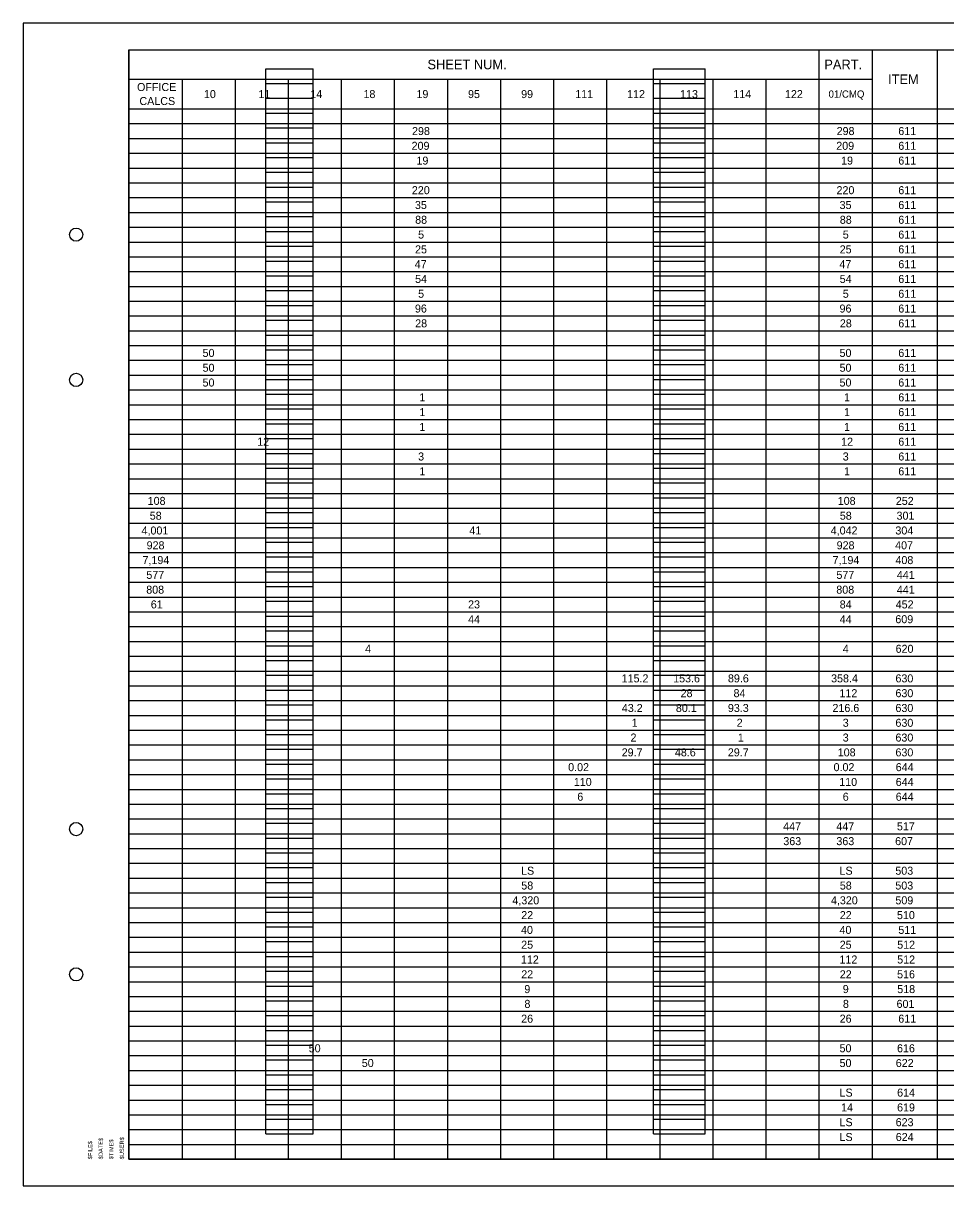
# Model space of a CAD drawing. Extents: x -16 to 102, y -13 to 9.
# Drawn here: x 27.05 to 44.51, y -12.91 to 9.09 of the extents above; entities that cross this region are included whole.
import ezdxf

# ---------------------------------------------------------------- set-up
doc = ezdxf.new("R2010")
doc.units = 0
for name, color, linetype in [('SH_Border', 7, 'Continuous'), ('SH_Cut_Line', 7, 'Continuous'), ('SH_Data', 7, 'Continuous'), ('TX_P_1', 7, 'Continuous'), ('TX_P_Misc', 7, 'Continuous')]:
    doc.layers.add(name, color=color, linetype=linetype)

msp = doc.modelspace()

# ---------------------------------------------------------------- linework, layer by layer
at = {"layer": 'SH_Border'}
msp.add_lwpolyline([(29.054, 8.593), (60.554, 8.593), (60.554, -12.407), (29.054, -12.407)], close=True, dxfattribs=at)
for centre in [(28.054, 5.093), (28.054, 2.343), (28.054, -6.157), (28.054, -8.907)]:
    msp.add_circle(centre, 0.125, dxfattribs=at)
at = {"layer": 'SH_Cut_Line'}
msp.add_lwpolyline([(27.054, -12.907), (61.054, -12.907), (61.054, 9.093), (27.054, 9.093)], close=True, dxfattribs=at)
at = {"layer": 'SH_Data'}
for p, q in [((31.642, -11.927), (31.642, 8.233)), ((31.642, 8.233), (32.542, 8.233)), ((32.542, -11.927), (32.542, 8.233)), ((38.982, -11.927), (38.982, 8.233)), ((38.982, 8.233), (39.962, 8.233)), ((39.962, -11.927), (39.962, 8.233)), ((31.642, 7.953), (32.542, 7.953)), ((38.982, 7.953), (39.962, 7.953)), ((31.642, 7.673), (32.542, 7.673)), ((38.982, 7.673), (39.962, 7.673)), ((31.642, 7.393), (32.542, 7.393)), ((38.982, 7.393), (39.962, 7.393)), ((31.642, 7.113), (32.542, 7.113)), ((38.982, 7.113), (39.962, 7.113)), ((31.642, 6.833), (32.542, 6.833)), ((38.982, 6.833), (39.962, 6.833)), ((31.642, 6.553), (32.542, 6.553)), ((38.982, 6.553), (39.962, 6.553)), ((31.642, 6.273), (32.542, 6.273)), ((38.982, 6.273), (39.962, 6.273)), ((31.642, 5.993), (32.542, 5.993)), ((38.982, 5.993), (39.962, 5.993)), ((31.642, 5.713), (32.542, 5.713)), ((38.982, 5.713), (39.962, 5.713)), ((31.642, 5.433), (32.542, 5.433)), ((38.982, 5.433), (39.962, 5.433)), ((31.642, 5.153), (32.542, 5.153)), ((38.982, 5.153), (39.962, 5.153)), ((31.642, 4.873), (32.542, 4.873)), ((38.982, 4.873), (39.962, 4.873)), ((31.642, 4.593), (32.542, 4.593)), ((38.982, 4.593), (39.962, 4.593)), ((31.642, 4.313), (32.542, 4.313)), ((38.982, 4.313), (39.962, 4.313)), ((31.642, 4.033), (32.542, 4.033)), ((38.982, 4.033), (39.962, 4.033)), ((31.642, 3.753), (32.542, 3.753)), ((38.982, 3.753), (39.962, 3.753)), ((31.642, 3.473), (32.542, 3.473)), ((38.982, 3.473), (39.962, 3.473)), ((31.642, 3.193), (32.542, 3.193)), ((38.982, 3.193), (39.962, 3.193)), ((31.642, 2.913), (32.542, 2.913)), ((38.982, 2.913), (39.962, 2.913)), ((31.642, 2.633), (32.542, 2.633)), ((38.982, 2.633), (39.962, 2.633)), ((31.642, 2.353), (32.542, 2.353)), ((38.982, 2.353), (39.962, 2.353)), ((31.642, 2.073), (32.542, 2.073)), ((38.982, 2.073), (39.962, 2.073)), ((31.642, 1.793), (32.542, 1.793)), ((38.982, 1.793), (39.962, 1.793)), ((31.642, 1.513), (32.542, 1.513)), ((38.982, 1.513), (39.962, 1.513)), ((31.642, 1.233), (32.542, 1.233)), ((38.982, 1.233), (39.962, 1.233)), ((31.642, 0.953), (32.542, 0.953)), ((38.982, 0.953), (39.962, 0.953)), ((31.642, 0.673), (32.542, 0.673)), ((38.982, 0.673), (39.962, 0.673)), ((31.642, 0.393), (32.542, 0.393)), ((38.982, 0.393), (39.962, 0.393)), ((31.642, 0.113), (32.542, 0.113)), ((38.982, 0.113), (39.962, 0.113)), ((31.642, -0.167), (32.542, -0.167)), ((38.982, -0.167), (39.962, -0.167)), ((31.642, -0.447), (32.542, -0.447)), ((38.982, -0.447), (39.962, -0.447)), ((31.642, -0.727), (32.542, -0.727)), ((38.982, -0.727), (39.962, -0.727)), ((31.642, -1.007), (32.542, -1.007)), ((38.982, -1.007), (39.962, -1.007)), ((31.642, -1.287), (32.542, -1.287)), ((38.982, -1.287), (39.962, -1.287)), ((31.642, -1.567), (32.542, -1.567)), ((38.982, -1.567), (39.962, -1.567)), ((31.642, -1.847), (32.542, -1.847)), ((38.982, -1.847), (39.962, -1.847)), ((31.642, -2.127), (32.542, -2.127)), ((38.982, -2.127), (39.962, -2.127)), ((31.642, -2.407), (32.542, -2.407)), ((38.982, -2.407), (39.962, -2.407)), ((31.642, -2.687), (32.542, -2.687)), ((38.982, -2.687), (39.962, -2.687)), ((31.642, -2.967), (32.542, -2.967)), ((38.982, -2.967), (39.962, -2.967)), ((31.642, -3.247), (32.542, -3.247)), ((38.982, -3.247), (39.962, -3.247)), ((31.642, -3.527), (32.542, -3.527)), ((38.982, -3.527), (39.962, -3.527)), ((31.642, -3.807), (32.542, -3.807)), ((38.982, -3.807), (39.962, -3.807)), ((31.642, -4.087), (32.542, -4.087)), ((38.982, -4.087), (39.962, -4.087)), ((31.642, -4.367), (32.542, -4.367)), ((38.982, -4.367), (39.962, -4.367)), ((31.642, -4.647), (32.542, -4.647)), ((38.982, -4.647), (39.962, -4.647)), ((31.642, -4.927), (32.542, -4.927)), ((38.982, -4.927), (39.962, -4.927)), ((31.642, -5.207), (32.542, -5.207)), ((38.982, -5.207), (39.962, -5.207)), ((31.642, -5.487), (32.542, -5.487)), ((38.982, -5.487), (39.962, -5.487)), ((31.642, -5.767), (32.542, -5.767)), ((38.982, -5.767), (39.962, -5.767)), ((31.642, -6.047), (32.542, -6.047)), ((38.982, -6.047), (39.962, -6.047)), ((31.642, -6.327), (32.542, -6.327)), ((38.982, -6.327), (39.962, -6.327)), ((31.642, -6.607), (32.542, -6.607)), ((38.982, -6.607), (39.962, -6.607)), ((31.642, -6.887), (32.542, -6.887)), ((38.982, -6.887), (39.962, -6.887)), ((31.642, -7.167), (32.542, -7.167)), ((38.982, -7.167), (39.962, -7.167)), ((31.642, -7.447), (32.542, -7.447)), ((38.982, -7.447), (39.962, -7.447)), ((31.642, -7.727), (32.542, -7.727)), ((38.982, -7.727), (39.962, -7.727)), ((31.642, -8.007), (32.542, -8.007)), ((38.982, -8.007), (39.962, -8.007)), ((31.642, -8.287), (32.542, -8.287)), ((38.982, -8.287), (39.962, -8.287)), ((31.642, -8.567), (32.542, -8.567)), ((38.982, -8.567), (39.962, -8.567)), ((31.642, -8.847), (32.542, -8.847)), ((38.982, -8.847), (39.962, -8.847)), ((31.642, -9.127), (32.542, -9.127)), ((38.982, -9.127), (39.962, -9.127)), ((31.642, -9.407), (32.542, -9.407)), ((38.982, -9.407), (39.962, -9.407)), ((31.642, -9.687), (32.542, -9.687)), ((38.982, -9.687), (39.962, -9.687)), ((31.642, -9.967), (32.542, -9.967)), ((38.982, -9.967), (39.962, -9.967)), ((31.642, -10.247), (32.542, -10.247)), ((38.982, -10.247), (39.962, -10.247)), ((31.642, -10.527), (32.542, -10.527)), ((38.982, -10.527), (39.962, -10.527)), ((31.642, -10.807), (32.542, -10.807)), ((38.982, -10.807), (39.962, -10.807)), ((31.642, -11.087), (32.542, -11.087)), ((38.982, -11.087), (39.962, -11.087)), ((31.642, -11.367), (32.542, -11.367)), ((38.982, -11.367), (39.962, -11.367)), ((31.642, -11.647), (32.542, -11.647)), ((38.982, -11.647), (39.962, -11.647)), ((31.642, -11.927), (32.542, -11.927)), ((38.982, -11.927), (39.962, -11.927)), ((29.642, -12.907), (29.642, -12.907))]:
    msp.add_line(p, q, dxfattribs=at)
at = {"layer": 'TX_P_1'}
for p, q in [((29.054, 8.593), (59.554, 8.593)), ((29.054, 8.593), (29.054, -12.405)), ((42.114, 8.593), (42.114, -12.405)), ((43.118, 8.593), (43.118, -12.405)), ((44.353, 8.593), (44.353, -12.405)), ((29.054, 8.033), (43.118, 8.033)), ((30.059, 8.033), (30.059, -12.405)), ((31.063, 8.033), (31.063, -12.405)), ((32.068, 8.033), (32.068, -12.405)), ((33.072, 8.033), (33.072, -12.405)), ((34.077, 8.033), (34.077, -12.405)), ((35.082, 8.033), (35.082, -12.405)), ((36.086, 8.033), (36.086, -12.405)), ((37.091, 8.033), (37.091, -12.405)), ((38.095, 8.033), (38.095, -12.405)), ((39.1, 8.033), (39.1, -12.405)), ((40.104, 8.033), (40.104, -12.405)), ((41.109, 8.033), (41.109, -12.405)), ((29.054, 7.473), (59.554, 7.473)), ((29.054, 7.193), (59.554, 7.193)), ((29.054, 6.913), (59.554, 6.913)), ((29.054, 6.633), (59.554, 6.633)), ((29.054, 6.353), (59.554, 6.353)), ((29.054, 6.073), (59.554, 6.073)), ((29.054, 5.793), (59.554, 5.793)), ((29.054, 5.513), (59.554, 5.513)), ((29.054, 5.233), (59.554, 5.233)), ((29.054, 4.953), (59.554, 4.953)), ((29.054, 4.674), (59.554, 4.674)), ((29.054, 4.394), (59.554, 4.394)), ((29.054, 4.114), (59.554, 4.114)), ((29.054, 3.834), (59.554, 3.834)), ((29.054, 3.554), (59.554, 3.554)), ((29.054, 3.274), (59.554, 3.274)), ((29.054, 2.994), (59.554, 2.994)), ((29.054, 2.714), (59.554, 2.714)), ((29.054, 2.434), (59.554, 2.434)), ((29.054, 2.154), (59.554, 2.154)), ((29.054, 1.874), (59.554, 1.874)), ((29.054, 1.594), (59.554, 1.594)), ((29.054, 1.314), (59.554, 1.314)), ((29.054, 1.034), (59.554, 1.034)), ((29.054, 0.754), (59.554, 0.754)), ((29.054, 0.474), (59.554, 0.474)), ((29.054, 0.194), (59.554, 0.194)), ((29.054, -0.086), (59.554, -0.086)), ((29.054, -0.366), (59.554, -0.366)), ((29.054, -0.646), (59.554, -0.646)), ((29.054, -0.926), (59.554, -0.926)), ((29.054, -1.206), (59.554, -1.206)), ((29.054, -1.486), (59.554, -1.486)), ((29.054, -1.766), (59.554, -1.766)), ((29.054, -2.046), (59.554, -2.046)), ((29.054, -2.326), (59.554, -2.326)), ((29.054, -2.606), (59.554, -2.606)), ((29.054, -2.886), (59.554, -2.886)), ((29.054, -3.166), (59.554, -3.166)), ((29.054, -3.446), (59.554, -3.446)), ((29.054, -3.726), (59.554, -3.726)), ((29.054, -4.005), (59.554, -4.005)), ((29.054, -4.285), (59.554, -4.285)), ((29.054, -4.565), (59.554, -4.565)), ((29.054, -4.845), (59.554, -4.845)), ((29.054, -5.125), (59.554, -5.125)), ((29.054, -5.405), (59.554, -5.405)), ((29.054, -5.685), (59.554, -5.685)), ((29.054, -5.965), (59.554, -5.965)), ((29.054, -6.245), (59.554, -6.245)), ((29.054, -6.525), (59.554, -6.525)), ((29.054, -6.805), (59.554, -6.805)), ((29.054, -7.085), (59.554, -7.085)), ((29.054, -7.365), (59.554, -7.365)), ((29.054, -7.645), (59.554, -7.645)), ((29.054, -7.925), (59.554, -7.925)), ((29.054, -8.205), (59.554, -8.205)), ((29.054, -8.485), (59.554, -8.485)), ((29.054, -8.765), (59.554, -8.765)), ((29.054, -9.045), (59.554, -9.045)), ((29.054, -9.325), (59.554, -9.325)), ((29.054, -9.605), (59.554, -9.605)), ((29.054, -9.885), (59.554, -9.885)), ((29.054, -10.165), (59.554, -10.165)), ((29.054, -10.445), (59.554, -10.445)), ((29.054, -10.725), (59.554, -10.725)), ((29.054, -11.005), (59.554, -11.005)), ((29.054, -11.285), (59.554, -11.285)), ((29.054, -11.565), (59.554, -11.565)), ((29.054, -11.845), (59.554, -11.845)), ((29.054, -12.125), (59.554, -12.125)), ((29.054, -12.405), (59.554, -12.405))]:
    msp.add_line(p, q, dxfattribs=at)

# ---------------------------------------------------------------- texts
for s, height, p in [('SHEET NUM.', 0.1818, (34.704, 8.222)), ('PART.', 0.1818, (42.215, 8.222)), ('OFFICE', 0.1515, (29.208, 7.81)), ('ITEM', 0.1818, (43.421, 7.942)), ('10', 0.1515, (30.474, 7.677)), ('11', 0.1515, (31.505, 7.677)), ('14', 0.1515, (32.487, 7.677)), ('18', 0.1515, (33.493, 7.677)), ('19', 0.1515, (34.496, 7.677)), ('95', 0.1515, (35.472, 7.677)), ('99', 0.1515, (36.477, 7.677)), ('111', 0.1515, (37.5, 7.677)), ('112', 0.1515, (38.482, 7.677)), ('113', 0.1515, (39.485, 7.677)), ('114', 0.1515, (40.492, 7.677)), ('122', 0.1515, (41.47, 7.677)), ('01/CMQ', 0.1364, (42.295, 7.685)), ('CALCS', 0.1515, (29.253, 7.545)), ('298', 0.1515, (34.412, 6.977)), ('298', 0.1515, (42.448, 6.977)), ('611', 0.1515, (43.615, 6.977)), ('209', 0.1515, (34.404, 6.698)), ('209', 0.1515, (42.441, 6.698)), ('611', 0.1515, (43.615, 6.698)), ('19', 0.1515, (34.496, 6.418)), ('19', 0.1515, (42.532, 6.418)), ('611', 0.1515, (43.615, 6.418)), ('220', 0.1515, (34.409, 5.858)), ('220', 0.1515, (42.446, 5.858)), ('611', 0.1515, (43.615, 5.858)), ('35', 0.1515, (34.467, 5.578)), ('35', 0.1515, (42.504, 5.578)), ('611', 0.1515, (43.615, 5.578)), ('88', 0.1515, (34.471, 5.298)), ('88', 0.1515, (42.508, 5.298)), ('611', 0.1515, (43.615, 5.298)), ('5', 0.152, (34.527, 5.018)), ('5', 0.152, (42.564, 5.018)), ('611', 0.1515, (43.615, 5.018)), ('25', 0.1515, (34.469, 4.738)), ('25', 0.1515, (42.506, 4.738)), ('611', 0.1515, (43.615, 4.738)), ('47', 0.1515, (34.464, 4.458)), ('47', 0.1515, (42.501, 4.458)), ('611', 0.1515, (43.615, 4.458)), ('54', 0.1515, (34.47, 4.178)), ('54', 0.1515, (42.506, 4.178)), ('611', 0.1515, (43.615, 4.178)), ('5', 0.152, (34.527, 3.898)), ('5', 0.152, (42.564, 3.898)), ('611', 0.1515, (43.615, 3.898)), ('96', 0.1515, (34.467, 3.618)), ('96', 0.1515, (42.503, 3.618)), ('611', 0.1515, (43.615, 3.618)), ('28', 0.1515, (34.472, 3.338)), ('28', 0.1515, (42.509, 3.338)), ('611', 0.1515, (43.615, 3.338)), ('50', 0.1515, (30.448, 2.778)), ('50', 0.1515, (42.503, 2.778)), ('611', 0.1515, (43.615, 2.778)), ('50', 0.1515, (30.448, 2.498)), ('50', 0.1515, (42.503, 2.498)), ('611', 0.1515, (43.615, 2.498)), ('50', 0.1515, (30.448, 2.218)), ('50', 0.1515, (42.503, 2.218)), ('611', 0.1515, (43.615, 2.218)), ('1', 0.152, (34.551, 1.938)), ('1', 0.152, (42.588, 1.938)), ('611', 0.1515, (43.615, 1.938)), ('1', 0.152, (34.551, 1.658)), ('1', 0.152, (42.588, 1.658)), ('611', 0.1515, (43.615, 1.658)), ('1', 0.152, (34.551, 1.378)), ('1', 0.152, (42.588, 1.378)), ('611', 0.1515, (43.615, 1.378)), ('12', 0.1515, (31.482, 1.098)), ('12', 0.1515, (42.533, 1.098)), ('611', 0.1515, (43.615, 1.098)), ('3', 0.152, (34.527, 0.818)), ('3', 0.152, (42.563, 0.818)), ('611', 0.1515, (43.615, 0.818)), ('1', 0.152, (34.551, 0.538)), ('1', 0.152, (42.588, 0.538)), ('611', 0.1515, (43.615, 0.538)), ('108', 0.1515, (29.409, -0.022)), ('108', 0.1515, (42.469, -0.022)), ('252', 0.1515, (43.568, -0.022)), ('58', 0.1515, (29.448, -0.302)), ('58', 0.1515, (42.508, -0.302)), ('301', 0.1515, (43.582, -0.302)), ('4,001', 0.1515, (29.293, -0.582)), ('41', 0.1515, (35.496, -0.582)), ('4,042', 0.1515, (42.336, -0.582)), ('304', 0.1515, (43.56, -0.582)), ('928', 0.1515, (29.389, -0.862)), ('928', 0.1515, (42.448, -0.862)), ('407', 0.1515, (43.555, -0.862)), ('7,194', 0.1515, (29.311, -1.142)), ('7,194', 0.1515, (42.371, -1.142)), ('408', 0.1515, (43.561, -1.142)), ('577', 0.1515, (29.384, -1.422)), ('577', 0.1515, (42.444, -1.422)), ('441', 0.1515, (43.588, -1.422)), ('808', 0.1515, (29.382, -1.702)), ('808', 0.1515, (42.442, -1.702)), ('441', 0.1515, (43.588, -1.702)), ('61', 0.1515, (29.468, -1.981)), ('23', 0.1515, (35.473, -1.981)), ('84', 0.1515, (42.506, -1.981)), ('452', 0.1515, (43.566, -1.981)), ('44', 0.1515, (35.474, -2.261)), ('44', 0.1515, (42.506, -2.261)), ('609', 0.1515, (43.559, -2.261)), ('4', 0.152, (33.524, -2.821)), ('4', 0.152, (42.565, -2.821)), ('620', 0.1515, (43.564, -2.821)), ('115.2', 0.1515, (38.379, -3.381)), ('153.6', 0.1515, (39.354, -3.381)), ('89.6', 0.1515, (40.391, -3.381)), ('358.4', 0.1515, (42.343, -3.381)), ('630', 0.1515, (43.561, -3.381)), ('28', 0.1515, (39.495, -3.661)), ('84', 0.1515, (40.497, -3.661)), ('112', 0.1515, (42.501, -3.661)), ('630', 0.1515, (43.561, -3.661)), ('43.2', 0.1515, (38.383, -3.941)), ('80.1', 0.1515, (39.405, -3.941)), ('93.3', 0.1515, (40.39, -3.941)), ('216.6', 0.1515, (42.369, -3.941)), ('630', 0.1515, (43.561, -3.941)), ('1', 0.152, (38.569, -4.221)), ('2', 0.152, (40.556, -4.221)), ('3', 0.152, (42.563, -4.221)), ('630', 0.1515, (43.561, -4.221)), ('2', 0.152, (38.547, -4.501)), ('1', 0.152, (40.578, -4.501)), ('3', 0.152, (42.563, -4.501)), ('630', 0.1515, (43.561, -4.501)), ('29.7', 0.1515, (38.38, -4.781)), ('48.6', 0.1515, (39.387, -4.781)), ('29.7', 0.1515, (40.389, -4.781)), ('108', 0.1515, (42.469, -4.781)), ('630', 0.1515, (43.561, -4.781)), ('0.02', 0.1515, (37.367, -5.061)), ('0.02', 0.1515, (42.39, -5.061)), ('644', 0.1515, (43.566, -5.061)), ('110', 0.1515, (37.474, -5.341)), ('110', 0.1515, (42.497, -5.341)), ('644', 0.1515, (43.566, -5.341)), ('6', 0.152, (37.54, -5.621)), ('6', 0.152, (42.563, -5.621)), ('644', 0.1515, (43.566, -5.621)), ('447', 0.1515, (41.437, -6.181)), ('447', 0.1515, (42.442, -6.181)), ('517', 0.1515, (43.589, -6.181)), ('363', 0.1515, (41.439, -6.461)), ('363', 0.1515, (42.443, -6.461)), ('607', 0.1515, (43.555, -6.461)), ('LS', 0.1515, (36.476, -7.021)), ('LS', 0.1515, (42.503, -7.021)), ('503', 0.1515, (43.559, -7.021)), ('58', 0.1515, (36.48, -7.301)), ('58', 0.1515, (42.508, -7.301)), ('503', 0.1515, (43.559, -7.301)), ('4,320', 0.1515, (36.312, -7.581)), ('4,320', 0.1515, (42.34, -7.581)), ('509', 0.1515, (43.56, -7.581)), ('22', 0.1515, (36.479, -7.861)), ('22', 0.1515, (42.507, -7.861)), ('510', 0.1515, (43.59, -7.861)), ('40', 0.1515, (36.475, -8.141)), ('40', 0.1515, (42.502, -8.141)), ('511', 0.1515, (43.616, -8.141)), ('25', 0.1515, (36.478, -8.421)), ('25', 0.1515, (42.506, -8.421)), ('512', 0.1515, (43.594, -8.421)), ('112', 0.1515, (36.473, -8.701)), ('112', 0.1515, (42.501, -8.701)), ('512', 0.1515, (43.594, -8.701)), ('22', 0.1515, (36.479, -8.981)), ('22', 0.1515, (42.507, -8.981)), ('516', 0.1515, (43.592, -8.981)), ('9', 0.152, (36.537, -9.261)), ('9', 0.152, (42.564, -9.261)), ('518', 0.1515, (43.595, -9.261)), ('8', 0.152, (36.539, -9.541)), ('8', 0.152, (42.567, -9.541)), ('601', 0.1515, (43.582, -9.541)), ('26', 0.1515, (36.478, -9.821)), ('26', 0.1515, (42.505, -9.821)), ('611', 0.1515, (43.615, -9.821)), ('50', 0.1515, (32.457, -10.381)), ('50', 0.1515, (42.503, -10.381)), ('616', 0.1515, (43.591, -10.381)), ('50', 0.1515, (33.461, -10.66)), ('50', 0.1515, (42.503, -10.66)), ('622', 0.1515, (43.567, -10.66)), ('LS', 0.1515, (42.503, -11.22)), ('614', 0.1515, (43.593, -11.22)), ('14', 0.1515, (42.533, -11.5)), ('619', 0.1515, (43.592, -11.5)), ('LS', 0.1515, (42.503, -11.78)), ('623', 0.1515, (43.565, -11.78)), ('LS', 0.1515, (42.503, -12.06)), ('624', 0.1515, (43.567, -12.06))]:
    msp.add_text(s, height=height, dxfattribs=at).set_placement(p)
at = {"layer": 'TX_P_Misc'}
for s, p in [('$FILE$', (28.359, -12.407)), ('$DATE$', (28.559, -12.407)), ('$TIME$', (28.759, -12.407)), ('$USER$', (28.959, -12.407))]:
    msp.add_text(s, height=0.078, rotation=90, dxfattribs=at).set_placement(p)

doc.saveas('drawing.dxf')
